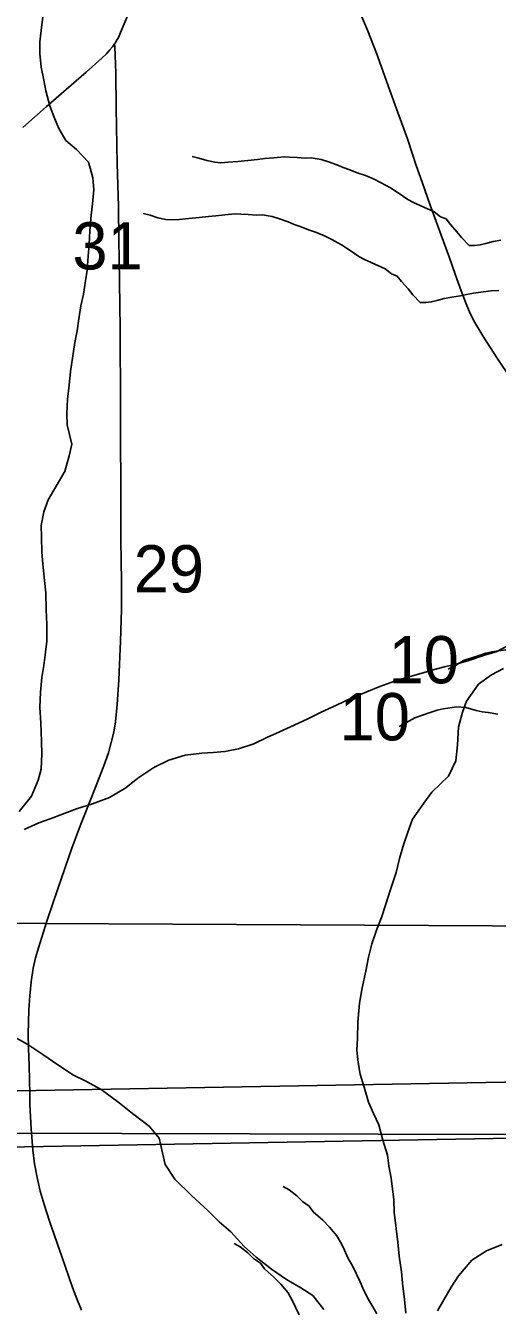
# Model space of a CAD drawing. Extents: x -21.1 to 50.3, y -4.9 to 22.1.
# Drawn here: x 5.889 to 6.307, y 16.789 to 17.924 of the extents above; entities that cross this region are included whole.
import ezdxf

# ---------------------------------------------------------------- set-up
doc = ezdxf.new("R2010")
doc.units = 0
for name, color, linetype in [('GM_X_County_Road', 7, 'Continuous'), ('GM_X_Minor_River', 7, 'Continuous'), ('GM_X_Section', 7, 'Continuous'), ('GM_X_Section_Text', 7, 'Continuous'), ('GM_X_State_Route', 7, 'Continuous'), ('GM_X_Township_Road', 7, 'Continuous')]:
    doc.layers.add(name, color=color, linetype=linetype)

msp = doc.modelspace()

# ---------------------------------------------------------------- linework, layer by layer
at = {"layer": 'GM_X_County_Road'}
msp.add_lwpolyline([(5.9385, 16.7861), (5.9348, 16.7946), (5.9304, 16.8062), (5.9214, 16.8326), (5.9101, 16.8649), (5.9054, 16.8797), (5.902, 16.8916), (5.8991, 16.9036), (5.897, 16.9158), (5.8955, 16.9281), (5.8939, 16.9467), (5.8928, 16.9684), (5.8927, 16.9777), (5.892, 17.0025), (5.8915, 17.0181), (5.8914, 17.0305), (5.8919, 17.0522), (5.8926, 17.0646), (5.8939, 17.0769), (5.8957, 17.0891), (5.8977, 17.0981), (5.9003, 17.107), (5.9079, 17.1307), (5.9177, 17.1602), (5.9299, 17.1954), (5.9379, 17.2167), (5.9487, 17.244), (5.9514, 17.2507), (5.9582, 17.2681), (5.9625, 17.2798), (5.9671, 17.298), (5.9685, 17.3072), (5.9701, 17.3227), (5.9715, 17.3445), (5.973, 17.3787), (5.9738, 17.4066), (5.9738, 17.4315), (5.9736, 17.4501), (5.9733, 17.4688), (5.9732, 17.4999), (5.9733, 17.5278), (5.9729, 17.5465), (5.9729, 17.5807), (5.973, 17.6086), (5.9728, 17.6335), (5.9726, 17.6553), (5.9717, 17.7175), (5.9716, 17.733), (5.9711, 17.7641), (5.9702, 17.8014), (5.9692, 17.8511), (5.9688, 17.8822), (5.9684, 17.8973), (5.9679, 17.9053), (5.9677, 17.9077)], dxfattribs=at)
at = {"layer": 'GM_X_Minor_River'}
for points in [[(5.9043, 17.9318), (5.9028, 17.9197), (5.9017, 17.9095), (5.9017, 17.8992), (5.9028, 17.8871), (5.9051, 17.8757), (5.907, 17.8662), (5.9104, 17.8529), (5.9141, 17.8435), (5.9183, 17.8328), (5.9247, 17.8222), (5.9342, 17.8143), (5.9448, 17.8029), (5.9486, 17.7892), (5.9494, 17.7786), (5.9482, 17.7661), (5.9471, 17.7559), (5.9459, 17.7422), (5.9452, 17.7304), (5.9444, 17.7198), (5.9436, 17.7073), (5.9421, 17.6978), (5.9402, 17.6861), (5.9379, 17.6758), (5.936, 17.6641), (5.9345, 17.6534), (5.9326, 17.6432), (5.9288, 17.6174), (5.9277, 17.6053), (5.9261, 17.5931), (5.9254, 17.5799), (5.9258, 17.5704), (5.9299, 17.5533), (5.9276, 17.5427), (5.9238, 17.529)], [(6.3098, 17.7339), (6.3029, 17.7327), (6.2965, 17.7308), (6.2915, 17.7296), (6.2866, 17.7292), (6.2816, 17.7292), (6.2751, 17.736), (6.2709, 17.7413), (6.2652, 17.7477), (6.2613, 17.7526), (6.2564, 17.7545), (6.2506, 17.759), (6.2384, 17.7647), (6.2323, 17.7673), (6.2273, 17.7699), (6.2197, 17.7752), (6.2121, 17.7801), (6.2033, 17.785), (6.1976, 17.788), (6.1899, 17.791), (6.1827, 17.7936), (6.1762, 17.7962), (6.1701, 17.7981), (6.1647, 17.8007), (6.1571, 17.8033), (6.1506, 17.8052), (6.1419, 17.8067), (6.1365, 17.8066), (6.1293, 17.807), (6.1228, 17.8073), (6.1179, 17.8077), (6.1088, 17.8069), (6.1008, 17.8061), (6.0943, 17.8053), (6.0859, 17.8045), (6.0768, 17.8036), (6.0684, 17.8028), (6.062, 17.8024), (6.0566, 17.8028), (6.0494, 17.8043), (6.0425, 17.8065), (6.0364, 17.808)], [(6.3079, 17.6893), (6.3011, 17.6889), (6.292, 17.6877), (6.2855, 17.6869), (6.2794, 17.6857), (6.2741, 17.6846), (6.2665, 17.6834), (6.2596, 17.6822), (6.2532, 17.6803), (6.2482, 17.6791), (6.2433, 17.6787), (6.2383, 17.6787), (6.2318, 17.6855), (6.2276, 17.6908), (6.2219, 17.6972), (6.218, 17.7021), (6.2131, 17.704), (6.2073, 17.7085), (6.1951, 17.7141), (6.189, 17.7168), (6.1841, 17.7194), (6.1764, 17.7247), (6.1688, 17.7296), (6.16, 17.7345), (6.1543, 17.7375), (6.1466, 17.7405), (6.1394, 17.7431), (6.1329, 17.7457), (6.1268, 17.7476), (6.1215, 17.7502), (6.1138, 17.7528), (6.1073, 17.7547), (6.0986, 17.7562), (6.0933, 17.7561), (6.086, 17.7565), (6.0796, 17.7568), (6.0746, 17.7572), (6.0655, 17.7563), (6.0575, 17.7555), (6.051, 17.7547), (6.0426, 17.7539), (6.0335, 17.7531), (6.0251, 17.7523), (6.0187, 17.7519), (6.0133, 17.7523), (6.0061, 17.7537), (5.9992, 17.756), (5.9931, 17.7575)], [(5.8832, 17.2278), (5.8943, 17.2414), (5.9001, 17.2554), (5.9029, 17.2652), (5.9033, 17.2789), (5.903, 17.2899), (5.9024, 17.3062), (5.9017, 17.3199), (5.9022, 17.3335), (5.9034, 17.3464), (5.905, 17.357), (5.9066, 17.3688), (5.9078, 17.3786), (5.9079, 17.3934), (5.9072, 17.4063), (5.9069, 17.4215), (5.9058, 17.4325), (5.9041, 17.4473), (5.9034, 17.4576), (5.9031, 17.4712), (5.9028, 17.4811), (5.9051, 17.4932), (5.909, 17.5038), (5.924, 17.5295)], [(5.8877, 17.2118), (5.9007, 17.2177), (5.9107, 17.2214), (5.9218, 17.2254), (5.934, 17.2301), (5.9481, 17.2345), (5.9634, 17.2403), (5.9776, 17.2488), (5.9883, 17.2574), (6.0025, 17.2667), (6.0159, 17.2733), (6.0304, 17.2777), (6.0449, 17.2794), (6.0552, 17.28), (6.0654, 17.2809), (6.0776, 17.2834), (6.091, 17.2878), (6.1025, 17.2933), (6.1139, 17.2984), (6.1269, 17.3043), (6.1388, 17.3098), (6.1507, 17.3157), (6.1644, 17.322), (6.1767, 17.3279), (6.1912, 17.3337), (6.2027, 17.3385), (6.2157, 17.3432), (6.2275, 17.3469), (6.2389, 17.3501), (6.25, 17.3534), (6.2599, 17.3559), (6.271, 17.3587), (6.2805, 17.3612), (6.2954, 17.3663), (6.3057, 17.3692), (6.3187, 17.3759)], [(6.3141, 17.3711), (6.3019, 17.3692), (6.2966, 17.368), (6.2905, 17.3661), (6.2768, 17.3614), (6.2696, 17.3572), (6.2632, 17.3538)], [(6.2257, 16.7833), (6.2246, 16.7954), (6.2228, 16.8099), (6.2217, 16.8201), (6.2199, 16.8338), (6.2185, 16.8463), (6.2171, 16.8585), (6.2153, 16.8729), (6.2149, 16.8839), (6.2128, 16.9029), (6.2106, 16.9139), (6.2095, 16.9234), (6.2054, 16.9367), (6.2017, 16.9504), (6.1969, 16.9603), (6.1927, 16.9702), (6.1887, 16.9835), (6.1853, 16.9952), (6.1835, 17.0055), (6.1824, 17.0165), (6.1829, 17.0268), (6.1833, 17.0412), (6.1846, 17.0579), (6.187, 17.0715), (6.1901, 17.0863), (6.1925, 17.0988), (6.1956, 17.1105), (6.1998, 17.1226), (6.2041, 17.134), (6.2079, 17.1457), (6.2118, 17.1578), (6.2172, 17.1738), (6.22, 17.1863), (6.2239, 17.1991), (6.2273, 17.2094), (6.2316, 17.2211), (6.2415, 17.2351), (6.2488, 17.2449), (6.2633, 17.2592), (6.2699, 17.2728), (6.2715, 17.2869), (6.2723, 17.3024), (6.2758, 17.3157), (6.2793, 17.3255), (6.2901, 17.3406), (6.3015, 17.3489), (6.3122, 17.3545)], [(6.307, 17.314), (6.2986, 17.3155), (6.2933, 17.3162), (6.2879, 17.3173), (6.2788, 17.3199), (6.2708, 17.3206), (6.2586, 17.3187), (6.2533, 17.3175), (6.2472, 17.3156), (6.2335, 17.3109), (6.2263, 17.3067), (6.2199, 17.3032)], [(6.1532, 16.7868), (6.1434, 16.799), (6.1328, 16.8059), (6.12, 16.8132), (6.1068, 16.8223), (6.0932, 16.8331), (6.0826, 16.8426), (6.0706, 16.8556), (6.0604, 16.8644), (6.0502, 16.8743), (6.0358, 16.8877), (6.0211, 16.9022), (6.0125, 16.9151), (6.0103, 16.9254), (6.0073, 16.9383), (5.9983, 16.949), (5.9836, 16.9604), (5.9719, 16.9696), (5.956, 16.9815), (5.9424, 16.9888), (5.9314, 16.9942), (5.9174, 17.0033), (5.9042, 17.0125), (5.891, 17.0213), (5.8789, 17.0282)], [(6.2001, 16.7828), (6.1963, 16.7889), (6.1917, 16.7969), (6.1875, 16.8056), (6.1851, 16.8113), (6.1821, 16.8181), (6.1786, 16.8249), (6.1744, 16.8325), (6.1713, 16.8393), (6.169, 16.8442), (6.1647, 16.8518), (6.1582, 16.8597), (6.1521, 16.8658), (6.1437, 16.8733), (6.1402, 16.8782), (6.1341, 16.8824), (6.1291, 16.8873), (6.1223, 16.8926), (6.1169, 16.8956)], [(6.1311, 16.7819), (6.128, 16.7888), (6.1257, 16.7937), (6.1215, 16.8013), (6.1149, 16.8092), (6.1088, 16.8153), (6.1004, 16.8228), (6.0969, 16.8277), (6.0908, 16.8319), (6.0859, 16.8368), (6.079, 16.8421), (6.0736, 16.8451)], [(6.2537, 16.7854), (6.2592, 16.7952), (6.2658, 16.8065), (6.2724, 16.8166), (6.2841, 16.8305), (6.2971, 16.8387), (6.3109, 16.8442)]]:
    msp.add_lwpolyline(points, dxfattribs=at)
at = {"layer": 'GM_X_Section'}
for points in [[(5.4574, 18.1459), (6.4683, 18.1347), (6.473, 17.126), (6.4154, 17.126), (5.4527, 17.1308)], [(5.8189, 17.992), (6.8357, 18.0145), (6.8441, 16.9976), (5.8315, 16.9794)], [(5.4882, 17.9725), (6.5167, 17.9592), (6.5415, 16.9412), (5.5202, 16.9439)], [(5.7756, 17.9415), (6.7924, 17.964), (6.8008, 16.9471), (5.7882, 16.9289)], [(5.4527, 17.1308), (6.4154, 17.126), (6.4119, 16.1246), (5.4495, 16.1332)], [(5.8315, 16.9794), (6.8441, 16.9976), (6.8586, 15.9725), (5.847, 15.9675)], [(6.5415, 16.9412), (6.5596, 15.9199), (6.5047, 15.9207), (5.5334, 15.9196), (5.5202, 16.9439)], [(5.7882, 16.9289), (6.8008, 16.9471), (6.8153, 15.9219), (5.8037, 15.917)]]:
    msp.add_lwpolyline(points, close=True, dxfattribs=at)
at = {"layer": 'GM_X_State_Route'}
msp.add_lwpolyline([(5.8865, 17.8336), (5.9073, 17.852), (5.9426, 17.8826), (5.9566, 17.8951), (5.9605, 17.8989), (5.9632, 17.902), (5.9658, 17.9051), (5.9677, 17.9077), (5.9682, 17.9084), (5.9701, 17.9115), (5.9711, 17.9135), (5.9731, 17.9178), (5.9828, 17.9408), (5.9932, 17.9653)], dxfattribs=at)
at = {"layer": 'GM_X_Township_Road'}
msp.add_lwpolyline([(6.3186, 17.6113), (6.3064, 17.6293), (6.2947, 17.6476), (6.2869, 17.6609), (6.2827, 17.669), (6.279, 17.6774), (6.2746, 17.689), (6.2694, 17.7036), (6.2642, 17.7182), (6.2589, 17.7328), (6.2473, 17.7649), (6.24, 17.7853), (6.2349, 17.8), (6.227, 17.8235), (6.2187, 17.8469), (6.2113, 17.8674), (6.1997, 17.8995), (6.1918, 17.9198), (6.1773, 17.9541)], dxfattribs=at)

# ---------------------------------------------------------------- texts
at = {"layer": 'GM_X_Section_Text'}
for s, p in [('31', (5.9304, 17.7079)), ('29', (5.9847, 17.4218)), ('10', (6.2103, 17.3413)), ('10', (6.167, 17.2908))]:
    msp.add_text(s, height=0.04186, rotation=0, dxfattribs=at).set_placement(p)

doc.saveas('drawing.dxf')
